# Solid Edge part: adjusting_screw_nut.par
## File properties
Title: Adjusting screw nut
Author: Abhinav Rai
Template: Normal.par
Last saved by: Rajat Kamboj
Revision: 23
Application: Solid Edge
Accuracy: 0.99
Material: aluminum
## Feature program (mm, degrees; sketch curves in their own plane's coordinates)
sketch for "unnamed RevolvedProtrusion 1" plane through (0, 0, 0) normal (0, -1, 0) x-axis (1, 0, 0)
  line (25.4, 9.7462) -> (74.676, 9.7462)
  line (76.2, 8.2222) -> (74.676, 9.7462)
  line (76.2, -26.8298) -> (76.2, 8.2222)
  line (76.2, -26.8298) -> (74.676, -28.3538)
  line (74.676, -28.3538) -> (47.625, -28.3538)
  line (47.625, -28.3538) -> (47.625, -60.1038)
  line (47.625, -60.1038) -> (25.4, -60.1038)
  line (25.4, -60.1038) -> (25.4, 9.7462)
revolve "unnamed RevolvedProtrusion 1" add full turn 360 deg
sketch for "Hole_1" plane through (76.2, 0, 0) normal (1, 0, 0) x-axis (0, 1, 0)
  hole centre (0, -9.3038) bore radius 9.5123
hole "Hole_1" diameter 19.0246 finite  VBottomAngle = 118 deg
pattern "unnamed Pattern 1" of "Hole_1"
pattern "unnamed Pattern 2"
sketch for "unnamed Cutout 1" plane through (0, 0, 9.7462) normal (0, 0, 1) x-axis (1, 0, 0)
extrude "unnamed Cutout 1" cut through along -normal
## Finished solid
Body 1: solid body, 16 faces, 16 edges, 4 vertices.
  Faces by surface: cylinder 7, cone 6, plane 3
  Edges by curve: circle 12, intersection 4
Bounding box of the edges (mm): 152.400 x 152.400 x 69.850, from (-76.2, -76.2, -60.1038) to (76.2, 76.2, 9.7462).
Cylindrical faces by radius (mm): R9.5123 x4, R38.1 x1, R47.625 x1, R76.2 x1
Conical faces (half-angle, radius in mm at the cone's reference point): 45 deg R74.676 x1, 45 deg R76.2 x1, 59 deg R9.5123 x4
Planar faces by outward normal: +z 1, -z 2
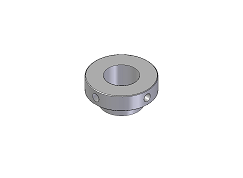
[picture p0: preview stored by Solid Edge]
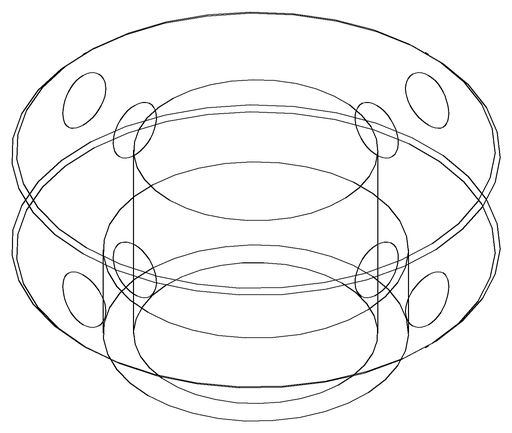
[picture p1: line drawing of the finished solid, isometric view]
